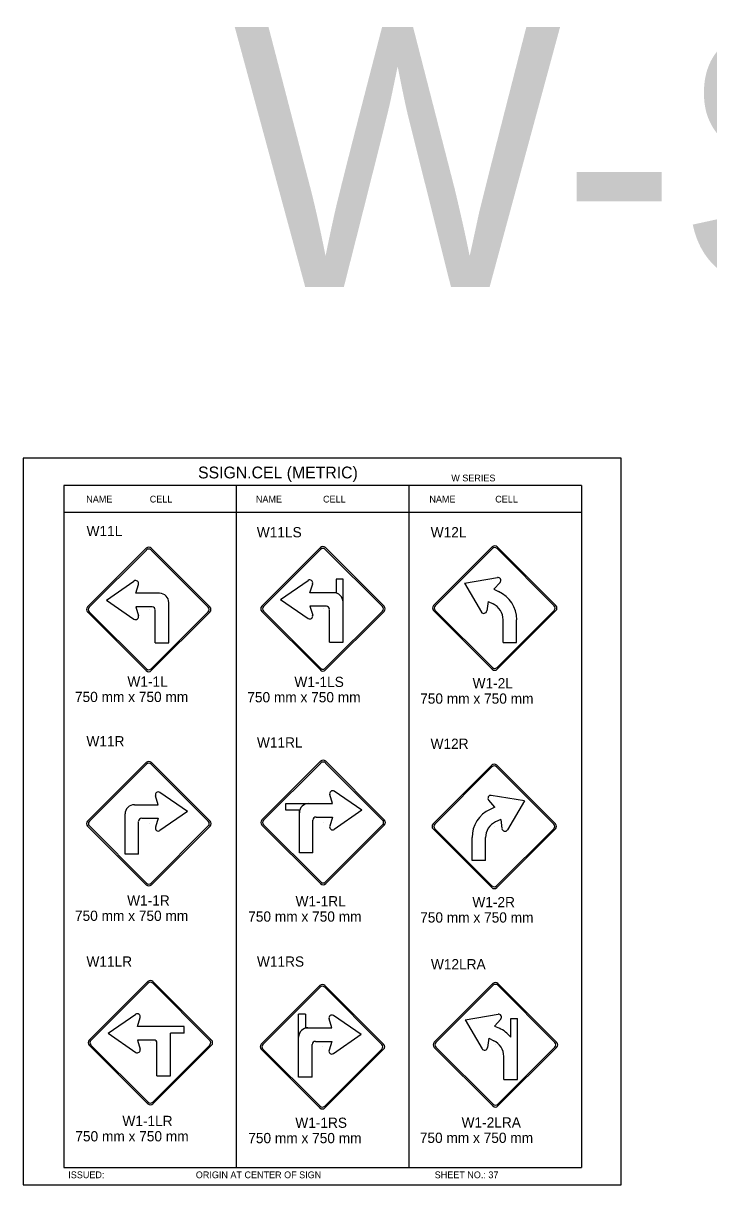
# Model space of a CAD drawing. Extents: x -12 to 6962, y -3756 to 679.
# Drawn here: x 1343.2 to 1544.2, y 225.3 to 565.9 of the extents above; entities that cross this region are included whole.
import ezdxf

# ---------------------------------------------------------------- set-up
doc = ezdxf.new("R2010")
doc.units = 0
for name, color, linetype in [('Level 1', 7, 'Continuous'), ('Level 2', 7, 'Continuous'), ('Level 3', 7, 'Continuous'), ('Level 62', 7, 'Continuous')]:
    doc.layers.add(name, color=color, linetype=linetype)

msp = doc.modelspace()

# ---------------------------------------------------------------- linework, layer by layer
at = {"layer": 'Level 1'}
for p, q in [((1506.83, 430.35), (1355.07, 430.35)), ((1355.07, 430.35), (1355.07, 230.35)), ((1405.66, 430.35), (1405.66, 230.35)), ((1456.24, 430.35), (1456.24, 230.35)), ((1506.83, 430.35), (1506.83, 230.35)), ((1405.66, 422.43), (1355.07, 422.43)), ((1456.24, 422.43), (1405.66, 422.43)), ((1506.83, 422.43), (1456.24, 422.43)), ((1362.54, 394.71), (1379.3, 411.46)), ((1380.67, 411.46), (1397.42, 394.71)), ((1413.62, 394.89), (1430.38, 411.65)), ((1431.75, 411.65), (1448.5, 394.89)), ((1463.99, 395.12), (1480.75, 411.88)), ((1482.12, 411.88), (1498.87, 395.12)), ((1367.57, 396.78), (1375.66, 402.36)), ((1418.65, 396.97), (1426.74, 402.55)), ((1434.99, 402.95), (1434.99, 398.94)), ((1436.97, 402.95), (1434.99, 402.95)), ((1436.97, 384.46), (1436.97, 402.95)), ((1472.54, 401.76), (1482.23, 403.41)), ((1481.14, 399.93), (1482.99, 401.96)), ((1376.17, 398.76), (1376.98, 401.37)), ((1383.15, 398.76), (1376.17, 398.76)), ((1427.25, 398.94), (1428.06, 401.56)), ((1434.99, 398.94), (1427.25, 398.94)), ((1472.54, 401.76), (1477.51, 393.26)), ((1481.14, 399.93), (1482.59, 399.28)), ((1367.57, 396.78), (1375.66, 391.18)), ((1385.89, 384.27), (1385.89, 396.05)), ((1418.65, 396.97), (1426.74, 391.36)), ((1479.47, 396.33), (1479.11, 393.62)), ((1479.47, 396.33), (1480.96, 395.65)), ((1379.3, 376.58), (1362.54, 393.34)), ((1380.99, 394.78), (1376.17, 394.78)), ((1376.17, 394.78), (1376.98, 392.16)), ((1380.08, 394.09), (1380.08, 394.09)), ((1397.42, 393.34), (1380.67, 376.58)), ((1381.9, 384.27), (1381.9, 393.86)), ((1430.38, 376.76), (1413.62, 393.52)), ((1432.07, 394.96), (1427.25, 394.96)), ((1427.25, 394.96), (1428.06, 392.35)), ((1431.16, 394.27), (1431.16, 394.27)), ((1448.5, 393.52), (1431.75, 376.76)), ((1432.98, 384.46), (1432.98, 394.05)), ((1480.75, 377), (1463.99, 393.75)), ((1481.53, 394.5), (1481.53, 394.5)), ((1498.87, 393.75), (1482.12, 377)), ((1483.91, 384.31), (1483.91, 391.03)), ((1487.86, 384.31), (1487.86, 391)), ((1381.9, 384.27), (1385.89, 384.27)), ((1432.98, 384.46), (1436.97, 384.46)), ((1483.91, 384.31), (1487.86, 384.31)), ((1362.58, 331.89), (1379.33, 348.65)), ((1380.7, 348.65), (1397.46, 331.89)), ((1413.68, 332.24), (1430.44, 348.99)), ((1431.81, 348.99), (1448.56, 332.24)), ((1463.86, 331.09), (1480.62, 347.85)), ((1481.99, 347.85), (1498.74, 331.09)), ((1442.47, 335.13), (1434.37, 340.71)), ((1382.76, 336.77), (1381.95, 339.38)), ((1391.36, 334.79), (1383.27, 340.37)), ((1433.87, 337.11), (1433.05, 339.72)), ((1481.51, 336.03), (1479.66, 338.06)), ((1490.12, 337.86), (1480.42, 339.5)), ((1490.12, 337.86), (1485.14, 329.38)), ((1373.04, 322.28), (1373.04, 334.05)), ((1375.78, 336.77), (1382.76, 336.77)), ((1391.36, 334.79), (1383.27, 329.18)), ((1420.14, 337.11), (1433.87, 337.11)), ((1420.14, 335.13), (1420.14, 337.11)), ((1424.15, 335.13), (1420.14, 335.13)), ((1424.15, 322.62), (1424.15, 335.13)), ((1442.47, 335.13), (1434.37, 329.52)), ((1481.51, 336.03), (1480.07, 335.37)), ((1379.33, 313.77), (1362.58, 330.52)), ((1377.03, 322.28), (1377.03, 331.87)), ((1377.94, 332.79), (1382.76, 332.79)), ((1380.12, 331.27), (1380.12, 331.27)), ((1397.46, 330.52), (1380.7, 313.77)), ((1382.76, 332.79), (1381.95, 330.17)), ((1430.44, 314.11), (1413.68, 330.87)), ((1428.13, 322.62), (1428.13, 332.21)), ((1429.05, 333.13), (1433.87, 333.13)), ((1431.22, 331.61), (1431.22, 331.61)), ((1448.56, 330.86), (1431.81, 314.11)), ((1433.87, 333.13), (1433.05, 330.51)), ((1481.4, 330.47), (1481.4, 330.47)), ((1483.19, 332.43), (1481.69, 331.74)), ((1483.19, 332.43), (1483.54, 329.74)), ((1480.62, 312.97), (1463.86, 329.72)), ((1474.79, 320.4), (1474.79, 327.1)), ((1478.75, 320.4), (1478.75, 327.12)), ((1498.74, 329.72), (1481.99, 312.97)), ((1377.03, 322.28), (1373.04, 322.28)), ((1428.13, 322.62), (1424.15, 322.62)), ((1478.75, 320.4), (1474.79, 320.4)), ((1363.04, 267.66), (1379.8, 284.42)), ((1381.17, 284.42), (1397.92, 267.66)), ((1413.47, 266.47), (1430.23, 283.22)), ((1431.6, 283.22), (1448.36, 266.47)), ((1464.19, 267.04), (1480.95, 283.8)), ((1482.32, 283.8), (1499.08, 267.04)), ((1368.07, 269.74), (1376.16, 275.32)), ((1376.67, 271.71), (1377.48, 274.33)), ((1423.94, 256.85), (1423.94, 275.35)), ((1425.92, 275.35), (1423.94, 275.35)), ((1425.92, 275.35), (1425.92, 271.34)), ((1433.66, 271.34), (1432.85, 273.95)), ((1442.26, 269.36), (1434.17, 274.94)), ((1472.74, 273.68), (1482.43, 275.33)), ((1472.74, 273.68), (1477.72, 265.18)), ((1481.34, 271.85), (1483.2, 273.88)), ((1486.12, 268.64), (1486.12, 274.09)), ((1486.12, 274.09), (1488.07, 274.09)), ((1488.07, 256.22), (1488.07, 274.09)), ((1368.07, 269.74), (1376.16, 264.13)), ((1390.39, 271.71), (1376.67, 271.71)), ((1386.39, 257.23), (1386.39, 269.73)), ((1390.39, 269.73), (1386.39, 269.73)), ((1390.39, 269.73), (1390.39, 271.71)), ((1425.92, 271.34), (1433.66, 271.34)), ((1442.26, 269.36), (1434.17, 263.75)), ((1481.34, 271.85), (1482.79, 271.19)), ((1379.8, 249.53), (1363.04, 266.29)), ((1381.49, 267.73), (1376.67, 267.73)), ((1376.67, 267.73), (1377.48, 265.12)), ((1380.58, 267.04), (1380.58, 267.04)), ((1397.92, 266.29), (1381.17, 249.53)), ((1382.4, 257.23), (1382.4, 266.82)), ((1427.92, 256.85), (1427.92, 266.44)), ((1428.84, 267.36), (1433.66, 267.36)), ((1431.01, 265.85), (1431.01, 265.85)), ((1433.66, 267.36), (1432.85, 264.74)), ((1479.67, 268.25), (1479.31, 265.53)), ((1479.67, 268.25), (1481.17, 267.56)), ((1481.73, 266.42), (1481.73, 266.42)), ((1430.23, 248.34), (1413.47, 265.1)), ((1448.36, 265.1), (1431.6, 248.34)), ((1480.95, 248.91), (1464.19, 265.67)), ((1499.08, 265.67), (1482.32, 248.91)), ((1484.11, 256.22), (1484.11, 262.95)), ((1382.4, 257.23), (1386.39, 257.23)), ((1427.92, 256.85), (1423.94, 256.85)), ((1484.11, 256.22), (1488.07, 256.22)), ((1355.07, 230.35), (1506.83, 230.35))]:
    msp.add_line(p, q, dxfattribs=at)
for centre, radius, start, end in [((1379.98, 410.78), 0.969, 45, 135), ((1431.06, 410.96), 0.969, 45, 135), ((1481.43, 411.19), 0.969, 45, 135), ((1376.13, 401.62), 0.88, 343.8088, 121.6584), ((1427.2, 401.81), 0.88, 343.8088, 121.6584), ((1482.33, 402.55), 0.877, 318.677, 97.1175), ((1383.15, 396.03), 2.73, 0, 90), ((1434.23, 396.21), 2.73, 0, 90), ((1478.78, 391.02), 9.1, 359.9807, 65.3304), ((1478.77, 391.01), 5.13, 0.0924, 64.7362), ((1363.23, 394.02), 0.969, 135, 225), ((1376.13, 391.93), 0.88, 238.3416, 16.1912), ((1380.99, 393.88), 0.909, 0, 90), ((1396.74, 394.02), 0.969, 315, 45), ((1414.31, 394.21), 0.969, 135, 225), ((1427.2, 392.11), 0.88, 238.3416, 16.1912), ((1432.07, 394.06), 0.909, 0, 90), ((1447.82, 394.21), 0.969, 315, 45), ((1464.68, 394.44), 0.969, 135, 225), ((1478.24, 393.76), 0.879, 213.1885, 351.7617), ((1498.19, 394.44), 0.969, 315, 45), ((1379.98, 377.27), 0.969, 225, 315), ((1431.06, 377.45), 0.969, 225, 315), ((1481.43, 377.68), 0.969, 225, 315), ((1380.02, 347.97), 0.969, 45, 135), ((1431.12, 348.31), 0.969, 45, 135), ((1481.3, 347.16), 0.969, 45, 135), ((1433.91, 339.97), 0.88, 58.3416, 196.1912), ((1382.81, 339.63), 0.88, 58.3416, 196.1912), ((1480.33, 338.64), 0.877, 82.8825, 221.323), ((1375.78, 334.04), 2.73, 90, 180), ((1426.88, 334.38), 2.73, 90, 180), ((1483.88, 327.11), 9.1, 114.6696, 180.0193), ((1363.26, 331.21), 0.969, 135, 225), ((1377.94, 331.89), 0.909, 90, 180), ((1396.77, 331.21), 0.969, 315, 45), ((1414.36, 331.55), 0.969, 135, 225), ((1429.04, 332.23), 0.909, 90, 180), ((1433.91, 330.27), 0.88, 163.8088, 301.6584), ((1447.88, 331.55), 0.969, 315, 45), ((1464.55, 330.41), 0.969, 135, 225), ((1483.89, 327.1), 5.13, 115.2638, 179.9076), ((1498.06, 330.41), 0.969, 315, 45), ((1382.81, 329.93), 0.88, 163.8088, 301.6584), ((1484.42, 329.85), 0.879, 188.2383, 326.8115), ((1380.02, 314.45), 0.969, 225, 315), ((1431.12, 314.79), 0.969, 225, 315), ((1481.3, 313.65), 0.969, 225, 315), ((1380.48, 283.73), 0.969, 45, 135), ((1430.91, 282.54), 0.969, 45, 135), ((1481.64, 283.11), 0.969, 45, 135), ((1376.62, 274.58), 0.88, 343.8088, 121.6584), ((1433.7, 274.2), 0.88, 58.3416, 196.1912), ((1482.53, 274.47), 0.877, 318.677, 97.1175), ((1426.68, 268.61), 2.73, 90, 180), ((1478.98, 262.94), 9.1, 38.3789, 65.3304), ((1363.73, 266.98), 0.969, 135, 225), ((1381.49, 266.83), 0.909, 0, 90), ((1397.24, 266.98), 0.969, 315, 45), ((1414.16, 265.78), 0.969, 135, 225), ((1428.84, 266.46), 0.909, 90, 180), ((1447.67, 265.78), 0.969, 315, 45), ((1464.88, 266.35), 0.969, 135, 225), ((1478.97, 262.92), 5.13, 0.0924, 64.7362), ((1498.39, 266.35), 0.969, 315, 45), ((1376.62, 264.88), 0.88, 238.3416, 16.1912), ((1433.7, 264.51), 0.88, 163.8088, 301.6584), ((1478.44, 265.67), 0.879, 213.1885, 351.7617), ((1380.48, 250.22), 0.969, 225, 315), ((1481.64, 249.6), 0.969, 225, 315), ((1430.91, 249.02), 0.969, 225, 315)]:
    msp.add_arc(centre, radius, start, end, dxfattribs=at)
at = {"layer": 'Level 3'}
for p, q in [((1463.49, 395.18), (1480.68, 412.38)), ((1482.18, 412.38), (1499.37, 395.18)), ((1379.24, 411.96), (1362.04, 394.77)), ((1397.92, 394.77), (1380.73, 411.96)), ((1430.31, 412.15), (1413.12, 394.95)), ((1449, 394.95), (1431.81, 412.15)), ((1362.04, 393.28), (1379.24, 376.08)), ((1380.73, 376.08), (1397.92, 393.27)), ((1413.12, 393.46), (1430.32, 376.27)), ((1431.81, 376.27), (1449, 393.46)), ((1480.68, 376.5), (1463.49, 393.69)), ((1499.37, 393.69), (1482.18, 376.5)), ((1379.27, 349.15), (1362.08, 331.96)), ((1397.96, 331.96), (1380.77, 349.15)), ((1413.18, 332.3), (1430.37, 349.49)), ((1431.87, 349.49), (1449.06, 332.3)), ((1463.36, 331.16), (1480.55, 348.35)), ((1482.05, 348.35), (1499.24, 331.16)), ((1362.08, 330.46), (1379.27, 313.27)), ((1380.77, 313.27), (1397.96, 330.46)), ((1430.37, 313.61), (1413.18, 330.8)), ((1449.06, 330.8), (1431.87, 313.61)), ((1480.56, 312.47), (1463.36, 329.66)), ((1499.24, 329.66), (1482.05, 312.47)), ((1379.73, 284.92), (1362.54, 267.72)), ((1398.42, 267.72), (1381.23, 284.92)), ((1430.17, 283.72), (1412.97, 266.53)), ((1448.85, 266.53), (1431.66, 283.72)), ((1463.7, 267.1), (1480.89, 284.29)), ((1482.38, 284.29), (1499.58, 267.1)), ((1362.54, 266.23), (1379.73, 249.04)), ((1381.23, 249.04), (1398.42, 266.23)), ((1412.97, 265.03), (1430.17, 247.84)), ((1431.66, 247.84), (1448.85, 265.03)), ((1480.89, 248.41), (1463.7, 265.61)), ((1499.58, 265.61), (1482.38, 248.41))]:
    msp.add_line(p, q, dxfattribs=at)
for centre, start, end in [((1379.98, 411.22), 45, 135), ((1431.06, 411.4), 45, 135), ((1481.43, 411.63), 45, 135), ((1464.24, 394.44), 135, 225), ((1498.62, 394.44), 315, 45), ((1362.79, 394.02), 135, 225), ((1397.18, 394.02), 315, 45), ((1413.87, 394.21), 135, 225), ((1448.26, 394.21), 315, 45), ((1379.98, 376.83), 225, 315), ((1431.06, 377.01), 225, 315), ((1481.43, 377.24), 225, 315), ((1380.02, 348.4), 45, 135), ((1431.12, 348.74), 45, 135), ((1481.3, 347.6), 45, 135), ((1362.83, 331.21), 135, 225), ((1397.21, 331.21), 315, 45), ((1413.93, 331.55), 135, 225), ((1448.31, 331.55), 315, 45), ((1464.11, 330.41), 135, 225), ((1498.49, 330.41), 315, 45), ((1431.12, 314.36), 225, 315), ((1380.02, 314.02), 225, 315), ((1481.3, 313.22), 225, 315), ((1380.48, 284.17), 45, 135), ((1430.91, 282.97), 45, 135), ((1481.64, 283.55), 45, 135), ((1363.29, 266.98), 135, 225), ((1397.67, 266.98), 315, 45), ((1413.72, 265.78), 135, 225), ((1448.11, 265.78), 315, 45), ((1464.44, 266.35), 135, 225), ((1498.83, 266.35), 315, 45), ((1380.48, 249.78), 225, 315), ((1430.91, 248.59), 225, 315), ((1481.64, 249.16), 225, 315)]:
    msp.add_arc(centre, 1.06, start, end, dxfattribs=at)
at = {"layer": 'Level 62'}
msp.add_lwpolyline([(1343.19, 225.31), (1518.46, 225.31), (1518.46, 438.4), (1343.19, 438.4)], close=True, dxfattribs=at)

# ---------------------------------------------------------------- texts
at = {"layer": 'Level 2'}
for s, p in [('W11L', (1361.77, 415.53)), ('W11LS', (1411.68, 415.17)), ('W12L', (1462.66, 415.17)), ('W11R', (1361.72, 353.88)), ('W11RL', (1411.72, 353.51)), ('W12R', (1462.62, 353.14)), ('W11LR', (1361.73, 289.28)), ('W11RS', (1411.72, 289.28)), ('W12LRA', (1462.73, 288.48))]:
    msp.add_text(s, height=3, dxfattribs=at).set_placement(p)
at = {"layer": 'Level 3'}
for s, height, p in [('W-SERIES CELLS', 76.1938, (1404.77, 488.61)), ('SSIGN.CEL (METRIC)', 3.4642, (1394.45, 432.46)), ('W SERIES', 1.979, (1468.7, 431.59)), ('NAME', 1.98, (1361.68, 425.39)), ('CELL', 1.98, (1380.29, 425.39)), ('NAME', 1.98, (1411.41, 425.39)), ('CELL', 1.98, (1431.1, 425.39)), ('NAME', 1.98, (1462.28, 425.39)), ('CELL', 1.98, (1481.58, 425.39)), ('W1-1L', 3, (1373.74, 371.38)), ('W1-1LS', 3, (1422.7, 371.29)), ('W1-2L', 3, (1474.96, 370.89)), ('750 mm x 750 mm', 3, (1358.36, 366.88)), ('750 mm x 750 mm', 3, (1408.89, 366.79)), ('750 mm x 750 mm', 3, (1459.58, 366.39)), ('W1-1R', 3, (1373.66, 307.19)), ('W1-1RL', 3, (1423.04, 306.97)), ('W1-2R', 3, (1474.88, 306.7)), ('750 mm x 750 mm', 3, (1358.36, 302.69)), ('750 mm x 750 mm', 3, (1409.16, 302.47)), ('750 mm x 750 mm', 3, (1459.58, 302.2)), ('W1-1LR', 3, (1372.27, 242.53)), ('W1-1RS', 3, (1422.97, 242)), ('W1-2LRA', 3, (1471.72, 242.08)), ('750 mm x 750 mm', 3, (1358.47, 238.03)), ('750 mm x 750 mm', 3, (1409.17, 237.5)), ('750 mm x 750 mm', 3, (1459.47, 237.58)), ('ISSUED:', 1.98, (1356.41, 227.23)), ('ORIGIN AT CENTER OF SIGN', 1.9795, (1393.8, 227.23)), ('SHEET NO.: 37', 1.9795, (1463.84, 227.23))]:
    msp.add_text(s, height=height, dxfattribs=at).set_placement(p)

doc.saveas('drawing.dxf')
